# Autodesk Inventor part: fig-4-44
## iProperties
Created: 2004-05
Part Number: fig-4-44
Document SubType Name: Modeling
Designer: CADCIM Technologies
Manufacturer: Standard
Standards Organization: Custom
Author: CADCIM Technologies
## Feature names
1. Revolution1
2. Revolution2
3. Revolution4
